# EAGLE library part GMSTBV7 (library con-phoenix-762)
PHOENIX
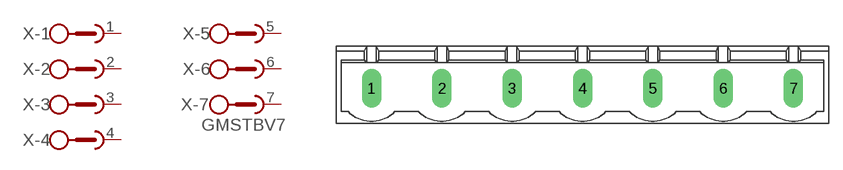
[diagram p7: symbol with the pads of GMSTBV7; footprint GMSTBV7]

Designator prefix X; gates -1=SKB -2=SKB -3=SKB -4=SKB -5=SKB -6=SKB -7=SKBV

## GMSTBV7 (OC_FARNELL: unknown; OC_NEWARK: unknown)  [GMSTBV7]
1  -1:1  pas
2  -2:1  pas
3  -3:1  pas
4  -4:1  pas
5  -5:1  pas
6  -6:1  pas
7  -7:1  pas

## Footprint GMSTBV7 (pad centres in mm)
PHOENIX
drill 1.397 long: 1 -22.86,0; 2 -15.24,0; 3 -7.62,0; 4 0,0; 5 7.62,0; 6 15.24,0; 7 22.86,0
